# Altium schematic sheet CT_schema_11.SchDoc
size 146 x 119 mm
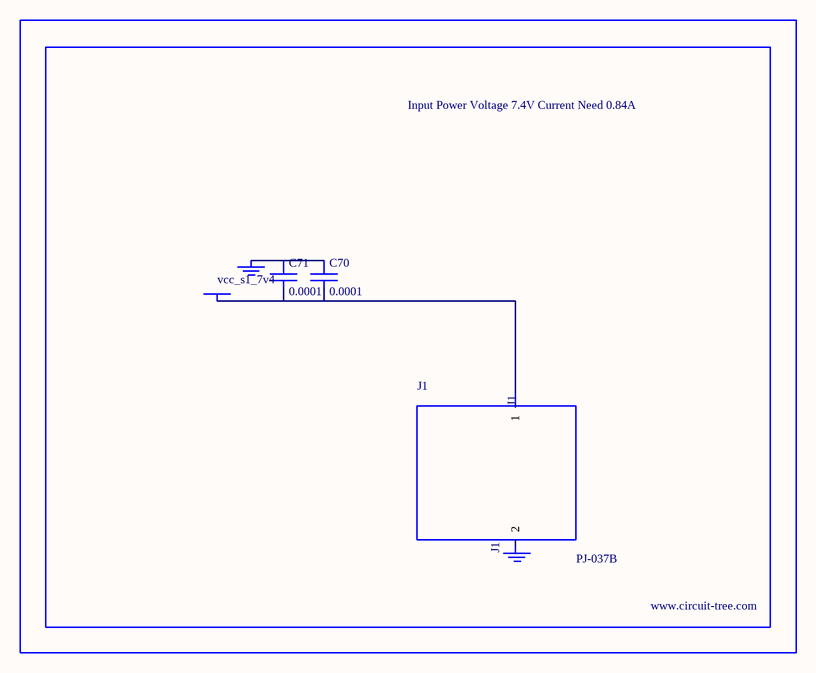
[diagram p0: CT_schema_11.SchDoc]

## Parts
BORDER10  (no value)
C70  0.0001  [EXV-9H]
C71  0.0001  [EXV-9H]
GND_INSTANCE_10_0  (no value)
GND_INSTANCE_10_1  (no value)
J1  PJ-037B  [PJ-037B_PACKAGE]
POWER_INSTANCE_10_0  vcc_s1_7v4

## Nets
NetC70_1: C70.1 C71.1 GND_INSTANCE_10_0.0(GND)
NetC70_2: C70.2 C71.2 J1.1 POWER_INSTANCE_10_0.0(PWR)

Not connected (* = marked no-connect by the designer): GND_INSTANCE_10_1 0(GND); J1 2

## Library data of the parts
BORDER10 = BORDER_PAGE10
C70 C71 = EDK107M035A9HAA
GND_INSTANCE_10_0 GND_INSTANCE_10_1 = GND
POWER_INSTANCE_10_0 = PWR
